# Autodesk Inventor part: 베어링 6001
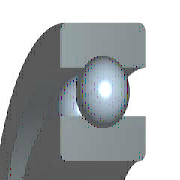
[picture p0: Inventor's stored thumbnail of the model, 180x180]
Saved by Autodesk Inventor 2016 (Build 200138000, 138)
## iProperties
IsCustomPart: 0
Created: 2015-10
Part Number: 베어링 6001
Material: Steel, Mild
Description: 깊은 그루브 볼 베어링
Document SubType Name: Modeling
Standard: KS B 2023
Designer: mdu
Standards Organization: KS
Language: ko-KR
Size Designation: 6001 - 12 x 28 x 8
Categories: <MemberInstance><Categories><Category DisplayName="샤프트 부품" InternalName="7f7aeb1f-a693-4053-b835-cee3144e0d98" Mnemonic="SHFT"><Category DisplayName="베어링" Inter
Density: 1 g/cm^3
Appearance: Steel
Author: mdu
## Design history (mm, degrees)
revolve "본체" stored, may be unused: angle "d6" = 90 deg
revolve "볼" stored, may be unused: angle "d7" = 90 deg
pattern_circular "IDS_ARRAYBALL[SIMPL:T]" dims angle "d3" = 360 deg
body "Solid1"
sketch "스케치" dims "d0" = 4.16 (= -0.26 x WD + 0.26 x BD)
  geometry: L1 (1.92, 10)-(6.08, 10); L2 (4, 10)-(4, 7.92); L3 (4, 10)-(4, 12.08); L4 (2.454, 8.608)-(0, 8.608); L5 (0, 6)-(8, 6); L6 (2.454, 11.392)-(0, 11.392); L7 (0, 14)-(8, 14); L8 (8, 6)-(8, 8.608); L9 (5.546, 8.608)-(8, 8.608); L10 (5.546, 11.392)-(8, 11.392); L11 (8, 14)-(8, 11.392); L12 (-1.4, 0)-(8.4, 0) reference; L13 (0, -0.3)-(0, 5.3) reference
  constraints: 22 end point, 4 point on line, 2 collinear, 2 perpendicular, 2 symmetric about line, 1 midpoint, 1 parallel, 14 other
  dimensions: "d9" = 12 diameter of L5 L12 (= WD); "d11" = 28 diameter of L7 L12 (= BD); "d12" = 8 distance between parallel lines of L8 L13 (= KB); "d13" = 17.216 diameter of L9 L12 (= 0.326 x BD + 0.674 x WD)
fillet "모깎기1" dims "d1" = 0.3 (= KRS)
other parameters: "WD" = 12 [user parameter; used in 5 equation terms], "BD" = 28 [user parameter; used in 5 equation terms], "KB" = 8 [user parameter; used in 1 equation term], "KRS" = 0.3 [user parameter; used in 1 equation term], "d4" = 0, "d5" = 0, "d8" = 0, "d14" = 0, "d15" = 0, "BBA" = 0 [user parameter], "BC0" = 2360000 [user parameter], "BC" = 5070000 [user parameter], "BR" = 14 (= 0.5 x BD) [user parameter], "WR" = 6 (= 0.5 x WD) [user parameter]
